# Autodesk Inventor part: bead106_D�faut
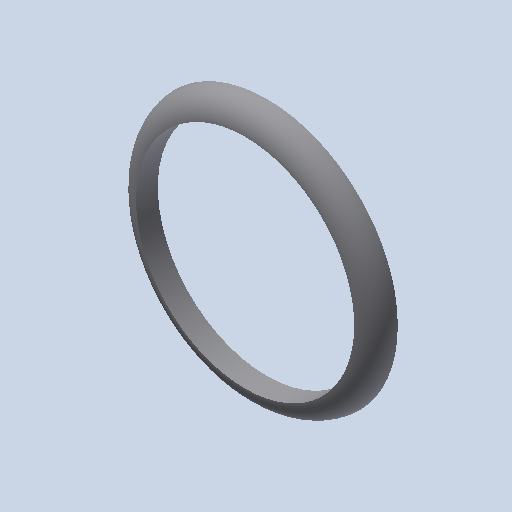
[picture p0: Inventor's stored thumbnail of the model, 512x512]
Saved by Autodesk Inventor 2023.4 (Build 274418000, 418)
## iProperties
Created: 2011-01
Part Number: bead106_D�faut
Document SubType Name: Modeling
Designer: eric
Density: 1 g/cm^3
Mass: 0.0252161 g
Surface Area: 1.19576 cm^2
Volume: 0.0252161 cm^3
Material: Générique
Appearance: Par défaut
Author: eric
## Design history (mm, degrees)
feature "Base1"
node "Corps solides"
node "Corps surfaciques"
node "Solide1"
